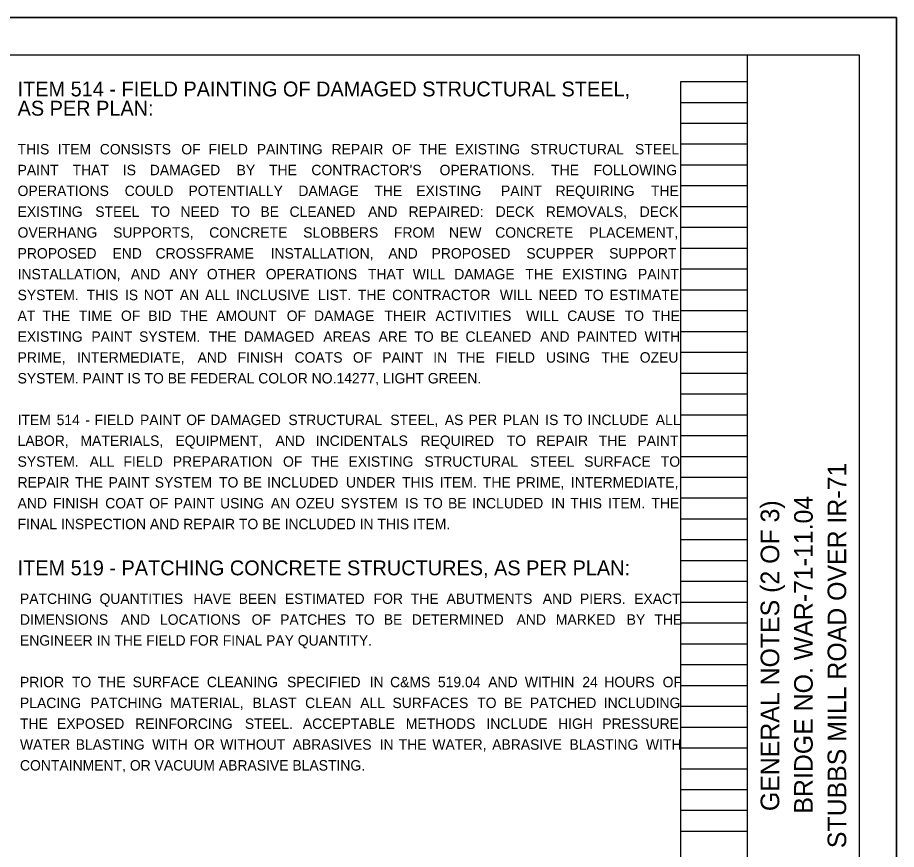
# Model space of a CAD drawing. Extents: x 0 to 34, y 0 to 22.
# Drawn here: x 22.19 to 34, y 10.81 to 22 of the extents above; entities that cross this region are included whole.
import ezdxf

# ---------------------------------------------------------------- set-up
doc = ezdxf.new("R2010")
doc.units = 0
for name, color, linetype in [('BR_P_Gen_Text', 7, 'Continuous'), ('SC_Scratch1', 7, 'Continuous'), ('SH_Border', 7, 'Continuous'), ('SH_Cut_Line', 7, 'Continuous'), ('SH_Data', 7, 'Continuous'), ('SH_Text', 7, 'Continuous')]:
    doc.layers.add(name, color=color, linetype=linetype)

msp = doc.modelspace()

# ---------------------------------------------------------------- linework, layer by layer
at = {"layer": 'SC_Scratch1'}
for p, q in [((31.1, 0.98), (31.1, 21.14)), ((31.1, 21.14), (32, 21.14)), ((32, 0.98), (32, 21.14)), ((31.1, 20.86), (32, 20.86)), ((31.1, 20.58), (32, 20.58)), ((31.1, 20.3), (32, 20.3)), ((31.1, 20.02), (32, 20.02)), ((31.1, 19.74), (32, 19.74)), ((31.1, 19.46), (32, 19.46)), ((31.1, 19.18), (32, 19.18)), ((31.1, 18.9), (32, 18.9)), ((31.1, 18.62), (32, 18.62)), ((31.1, 18.34), (32, 18.34)), ((31.1, 18.06), (32, 18.06)), ((31.1, 17.78), (32, 17.78)), ((31.1, 17.5), (32, 17.5)), ((31.1, 17.22), (32, 17.22)), ((31.1, 16.94), (32, 16.94)), ((31.1, 16.66), (32, 16.66)), ((31.1, 16.38), (32, 16.38)), ((31.1, 16.1), (32, 16.1)), ((31.1, 15.82), (32, 15.82)), ((31.1, 15.54), (32, 15.54)), ((31.1, 15.26), (32, 15.26)), ((31.1, 14.98), (32, 14.98)), ((31.1, 14.7), (32, 14.7)), ((31.1, 14.42), (32, 14.42)), ((31.1, 14.14), (32, 14.14)), ((31.1, 13.86), (32, 13.86)), ((31.1, 13.58), (32, 13.58)), ((31.1, 13.3), (32, 13.3)), ((31.1, 13.02), (32, 13.02)), ((31.1, 12.74), (32, 12.74)), ((31.1, 12.46), (32, 12.46)), ((31.1, 12.18), (32, 12.18)), ((31.1, 11.9), (32, 11.9)), ((31.1, 11.62), (32, 11.62)), ((31.1, 11.34), (32, 11.34)), ((31.1, 11.06), (32, 11.06))]:
    msp.add_line(p, q, dxfattribs=at)
msp.add_lwpolyline([(0, 22), (34, 22), (34, 0), (0, 0)], close=True, dxfattribs=at)
at = {"layer": 'SH_Border'}
msp.add_line((32, 0.5), (32, 21.5), dxfattribs=at)
msp.add_lwpolyline([(1.5, 21.5), (33.5, 21.5), (33.5, 0.5), (1.5, 0.5)], close=True, dxfattribs=at)
at = {"layer": 'SH_Cut_Line'}
msp.add_lwpolyline([(0, 0), (34, 0), (34, 22), (0, 22)], close=True, dxfattribs=at)

# ---------------------------------------------------------------- texts
at = {"layer": 'BR_P_Gen_Text'}
for s, p in [('ITEM 514 - FIELD PAINTING OF DAMAGED STRUCTURAL STEEL, ', (22.187, 20.94)), ('AS PER PLAN:', (22.187, 20.681)), ('ITEM 519 - PATCHING CONCRETE STRUCTURES, AS PER PLAN:', (22.187, 14.5))]:
    msp.add_text(s, height=0.2, dxfattribs=at).set_placement(p)
at = {"layer": 'SH_Data'}
for s, p in [('STUBBS MILL ROAD OVER IR-71', (33.325, 10.831)), ('GENERAL NOTES (2 OF 3)', (32.425, 11.329)), ('BRIDGE NO. WAR-71-11.04', (32.875, 11.296))]:
    msp.add_text(s, height=0.25, rotation=90, dxfattribs=at).set_placement(p)
at = {"layer": 'SH_Text'}
for s, p in [('THIS ', (22.187, 20.16)), ('ITEM ', (22.728, 20.16)), ('CONSISTS ', (23.292, 20.16)), ('OF ', (24.388, 20.16)), ('FIELD ', (24.752, 20.16)), ('PAINTING ', (25.402, 20.16)), ('REPAIR ', (26.408, 20.16)), ('OF ', (27.218, 20.16)), ('THE ', (27.582, 20.16)), ('EXISTING ', (28.069, 20.16)), ('STRUCTURAL ', (29.079, 20.16)), ('STEEL ', (30.486, 20.16)), ('PAINT ', (22.187, 19.88)), ('THAT ', (22.926, 19.88)), ('IS ', (23.601, 19.88)), ('DAMAGED ', (23.964, 19.88)), ('BY ', (25.131, 19.88)), ('THE ', (25.567, 19.88)), ("CONTRACTOR'S ", (26.136, 19.88)), ('OPERATIONS. ', (27.859, 19.88)), ('THE ', (29.359, 19.88)), ('FOLLOWING ', (29.929, 19.88)), ('OPERATIONS ', (22.187, 19.6)), ('COULD ', (23.627, 19.6)), ('POTENTIALLY ', (24.484, 19.6)), ('DAMAGE ', (25.961, 19.6)), ('THE ', (26.982, 19.6)), ('EXISTING  ', (27.545, 19.6)), ('PAINT ', (28.685, 19.6)), ('REQUIRING ', (29.419, 19.6)), ('THE ', (30.7, 19.6)), ('EXISTING ', (22.187, 19.32)), ('STEEL ', (23.231, 19.32)), ('TO ', (23.978, 19.32)), ('NEED ', (24.377, 19.32)), ('TO ', (25.052, 19.32)), ('BE ', (25.451, 19.32)), ('CLEANED ', (25.843, 19.32)), ('AND ', (26.898, 19.32)), ('REPAIRED: ', (27.442, 19.32)), ('DECK ', (28.613, 19.32)), ('REMOVALS, ', (29.287, 19.32)), ('DECK ', (30.549, 19.32)), ('OVERHANG ', (22.187, 19.04)), ('SUPPORTS, ', (23.471, 19.04)), ('CONCRETE ', (24.763, 19.04)), ('SLOBBERS ', (26.026, 19.04)), ('FROM ', (27.245, 19.04)), ('NEW ', (27.986, 19.04)), ('CONCRETE ', (28.607, 19.04)), ('PLACEMENT, ', (29.87, 19.04)), ('PROPOSED ', (22.187, 18.76)), ('CROSSFRAME ', (24.041, 18.76)), ('INSTALLATION, ', (25.588, 18.76)), ('PROPOSED ', (27.751, 18.76)), ('SCUPPER ', (29.026, 18.76)), ('SUPPORT ', (30.138, 18.76)), ('END ', (23.462, 18.76)), ('AND ', (27.171, 18.76)), ('INSTALLATION, ', (22.187, 18.48)), ('AND ', (23.709, 18.48)), ('ANY ', (24.228, 18.48)), ('OTHER ', (24.732, 18.48)), ('OPERATIONS ', (25.523, 18.48)), ('THAT ', (26.896, 18.48)), ('WILL ', (27.498, 18.48)), ('DAMAGE ', (28.057, 18.48)), ('THE ', (29.011, 18.48)), ('EXISTING ', (29.508, 18.48)), ('PAINT ', (30.526, 18.48)), ('SYSTEM. ', (22.187, 18.2)), ('THIS ', (23.115, 18.2)), ('IS ', (23.63, 18.2)), ('NOT ', (23.884, 18.2)), ('AN ', (24.367, 18.2)), ('ALL ', (24.708, 18.2)), ('INCLUSIVE ', (25.122, 18.2)), ('LIST. ', (26.225, 18.2)), ('THE ', (26.761, 18.2)), ('CONTRACTOR ', (27.222, 18.2)), ('WILL ', (28.669, 18.2)), ('NEED ', (29.191, 18.2)), ('TO ', (29.804, 18.2)), ('ESTIMATE ', (30.142, 18.2)), ('AT ', (22.187, 17.92)), ('THE ', (22.521, 17.92)), ('TIME ', (23.011, 17.92)), ('OF ', (23.577, 17.92)), ('BID ', (23.944, 17.92)), ('THE ', (24.369, 17.92)), ('AMOUNT ', (24.859, 17.92)), ('OF ', (25.805, 17.92)), ('DAMAGE ', (26.172, 17.92)), ('THEIR ', (27.119, 17.92)), ('ACTIVITIES  ', (27.805, 17.92)), ('WILL ', (29.023, 17.92)), ('CAUSE ', (29.575, 17.92)), ('TO ', (30.347, 17.92)), ('THE ', (30.714, 17.92)), ('EXISTING ', (22.187, 17.64)), ('PAINT ', (23.179, 17.64)), ('SYSTEM. ', (23.82, 17.64)), ('THE ', (24.757, 17.64)), ('DAMAGED ', (25.228, 17.64)), ('AREAS ', (26.296, 17.64)), ('ARE ', (27.039, 17.64)), ('TO ', (27.52, 17.64)), ('BE ', (27.867, 17.64)), ('CLEANED ', (28.207, 17.64)), ('AND ', (29.211, 17.64)), ('PAINTED ', (29.703, 17.64)), ('WITH ', (30.615, 17.64)), ('PRIME, ', (22.187, 17.36)), ('INTERMEDIATE, ', (22.985, 17.36)), ('AND ', (24.606, 17.36)), ('FINISH ', (25.144, 17.36)), ('COATS ', (25.91, 17.36)), ('OF ', (26.695, 17.36)), ('PAINT ', (27.088, 17.36)), ('IN ', (27.774, 17.36)), ('THE ', (28.094, 17.36)), ('FIELD ', (28.611, 17.36)), ('USING ', (29.29, 17.36)), ('THE ', (30.034, 17.36)), ('OZEU ', (30.55, 17.36)), ('SYSTEM. PAINT IS TO BE FEDERAL COLOR NO.14277, LIGHT GREEN.', (22.187, 17.08)), ('ITEM ', (22.187, 16.52)), ('514 ', (22.712, 16.52)), ('FIELD ', (23.22, 16.52)), ('PAINT ', (23.833, 16.52)), ('OF ', (24.453, 16.52)), ('DAMAGED ', (24.779, 16.52)), ('STRUCTURAL ', (25.827, 16.52)), ('STEEL, ', (27.197, 16.52)), ('AS ', (27.929, 16.52)), ('PER ', (28.249, 16.52)), ('PLAN ', (28.709, 16.52)), ('IS ', (29.279, 16.52)), ('TO ', (29.522, 16.52)), ('INCLUDE ', (29.848, 16.52)), ('ALL ', (30.765, 16.52)), ('- ', (23.097, 16.52)), ('LABOR, ', (22.187, 16.24)), ('MATERIALS, ', (23.032, 16.24)), ('EQUIPMENT, ', (24.309, 16.24)), ('AND ', (25.654, 16.24)), ('INCIDENTALS ', (26.195, 16.24)), ('REQUIRED ', (27.602, 16.24)), ('TO ', (28.762, 16.24)), ('REPAIR ', (29.158, 16.24)), ('THE ', (30, 16.24)), ('PAINT ', (30.519, 16.24)), ('SYSTEM. ', (22.187, 15.96)), ('ALL ', (23.155, 15.96)), ('FIELD ', (23.609, 15.96)), ('PREPARATION ', (24.273, 15.96)), ('OF ', (25.755, 15.96)), ('THE ', (26.133, 15.96)), ('EXISTING ', (26.634, 15.96)), ('STRUCTURAL ', (27.656, 15.96)), ('STEEL ', (29.077, 15.96)), ('SURFACE ', (29.803, 15.96)), ('TO ', (30.833, 15.96)), ('REPAIR ', (22.187, 15.68)), ('THE ', (22.96, 15.68)), ('PAINT ', (23.41, 15.68)), ('SYSTEM ', (24.031, 15.68)), ('TO ', (24.894, 15.68)), ('BE ', (25.221, 15.68)), ('INCLUDED ', (25.541, 15.68)), ('UNDER ', (26.601, 15.68)), ('THIS ', (27.355, 15.68)), ('ITEM. ', (27.86, 15.68)), ('THE ', (28.441, 15.68)), ('PRIME, ', (28.891, 15.68)), ('INTERMEDIATE, ', (29.624, 15.68)), ('AND ', (22.187, 15.4)), ('FINISH ', (22.662, 15.4)), ('COAT ', (23.365, 15.4)), ('OF ', (23.956, 15.4)), ('PAINT ', (24.286, 15.4)), ('USING ', (24.909, 15.4)), ('AN ', (25.591, 15.4)), ('OZEU ', (25.925, 15.4)), ('SYSTEM ', (26.53, 15.4)), ('IS ', (27.397, 15.4)), ('TO ', (27.643, 15.4)), ('BE ', (27.973, 15.4)), ('INCLUDED ', (28.296, 15.4)), ('IN ', (29.358, 15.4)), ('THIS ', (29.616, 15.4)), ('ITEM. ', (30.123, 15.4)), ('THE ', (30.707, 15.4)), ('FINAL INSPECTION AND REPAIR TO BE INCLUDED IN THIS ITEM.', (22.187, 15.12)), ('PATCHING ', (22.219, 14.115)), ('QUANTITIES ', (23.288, 14.115)), ('HAVE ', (24.55, 14.115)), ('BEEN ', (25.159, 14.115)), ('ESTIMATED ', (25.78, 14.115)), ('FOR ', (26.972, 14.115)), ('THE ', (27.473, 14.115)), ('ABUTMENTS ', (27.952, 14.115)), ('AND ', (29.246, 14.115)), ('PIERS. ', (29.746, 14.115)), ('EXACT ', (30.475, 14.115)), ('DIMENSIONS ', (22.219, 13.835)), ('AND ', (23.573, 13.835)), ('LOCATIONS ', (24.101, 13.835)), ('OF ', (25.333, 13.835)), ('PATCHES ', (25.716, 13.835)), ('TO ', (26.726, 13.835)), ('BE ', (27.109, 13.835)), ('DETERMINED ', (27.485, 13.835)), ('AND ', (28.894, 13.835)), ('MARKED ', (29.422, 13.835)), ('BY ', (30.374, 13.835)), ('THE ', (30.747, 13.835)), ('ENGINEER IN THE FIELD FOR FINAL PAY QUANTITY.', (22.219, 13.555)), ('PRIOR ', (22.219, 12.995)), ('TO ', (22.917, 12.995)), ('THE ', (23.263, 12.995)), ('SURFACE ', (23.733, 12.995)), ('CLEANING ', (24.731, 12.995)), ('SPECIFIED ', (25.809, 12.995)), ('IN ', (26.92, 12.995)), ('C&MS ', (27.194, 12.995)), ('519.04 ', (27.837, 12.995)), ('AND ', (28.513, 12.995)), ('WITHIN ', (29.005, 12.995)), ('24 ', (29.778, 12.995)), ('HOURS ', (30.074, 12.995)), ('OF ', (30.858, 12.995)), ('PLACING ', (22.219, 12.715)), ('PATCHING ', (23.166, 12.715)), ('MATERIAL, ', (24.237, 12.715)), ('BLAST ', (25.344, 12.715)), ('CLEAN ', (26.052, 12.715)), ('ALL ', (26.793, 12.715)), ('SURFACES ', (27.226, 12.715)), ('TO ', (28.365, 12.715)), ('BE ', (28.722, 12.715)), ('PATCHED ', (29.072, 12.715)), ('INCLUDING ', (30.066, 12.715)), ('THE ', (22.219, 12.435)), ('EXPOSED ', (22.716, 12.435)), ('REINFORCING ', (23.767, 12.435)), ('STEEL. ', (25.242, 12.435)), ('ACCEPTABLE ', (26.021, 12.435)), ('METHODS ', (27.405, 12.435)), ('INCLUDE ', (28.489, 12.435)), ('HIGH ', (29.453, 12.435)), ('PRESSURE ', (30.047, 12.435)), ('WATER ', (22.219, 12.155)), ('BLASTING ', (22.968, 12.155)), ('WITH ', (23.996, 12.155)), ('OR ', (24.557, 12.155)), ('WITHOUT ', (24.911, 12.155)), ('ABRASIVES ', (25.884, 12.155)), ('IN ', (27.054, 12.155)), ('THE ', (27.31, 12.155)), ('WATER, ', (27.762, 12.155)), ('ABRASIVE ', (28.566, 12.155)), ('BLASTING ', (29.605, 12.155)), ('WITH ', (30.633, 12.155)), ('CONTAINMENT, OR VACUUM ABRASIVE BLASTING.', (22.219, 11.875))]:
    msp.add_text(s, height=0.14, dxfattribs=at).set_placement(p)

doc.saveas('drawing.dxf')
